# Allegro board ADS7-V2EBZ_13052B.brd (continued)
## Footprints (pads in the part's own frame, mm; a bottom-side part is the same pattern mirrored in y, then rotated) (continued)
CNTYCO292304
  rect 1.524x1.524 hole 1.016: 1(0,0)
  round 1.524 hole 1.016: 2(2.5,0) 3(2.5,2) 4(0,2)
  round 2.921 hole 2.413: G1(-4.77,4.71) G2(7.27,4.71)
CPLSML327W327H413
  rect 4.039x1.397 smd: N(3.43,0) P(-3.43,0)
CSPBGA208
  round 0.356 smd: A1(-7.6,-7.6) A2(-7.6,-6.8) A3(-7.6,-6) A4(-7.6,-5.2) A5(-7.6,-4.4) A6(-7.6,-3.6) A7(-7.6,-2.8) A8(-7.6,-2) A9(-7.6,-1.2) A10(-7.6,-0.4) A11(-7.6,0.4) A12(-7.6,1.2) A13(-7.6,2) A14(-7.6,2.8) A15(-7.6,3.6) A16(-7.6,4.4) A17(-7.6,5.2) A18(-7.6,6) A19(-7.6,6.8) A20(-7.6,7.6) B1(-6.8,-7.6) B2(-6.8,-6.8) B3(-6.8,-6) B4(-6.8,-5.2) B5(-6.8,-4.4) B6(-6.8,-3.6) B7(-6.8,-2.8) B8(-6.8,-2) B9(-6.8,-1.2) B10(-6.8,-0.4) B11(-6.8,0.4) B12(-6.8,1.2) B13(-6.8,2) B14(-6.8,2.8) B15(-6.8,3.6) B16(-6.8,4.4) B17(-6.8,5.2) B18(-6.8,6) B19(-6.8,6.8) B20(-6.8,7.6) C1(-6,-7.6) C2(-6,-6.8) C19(-6,6.8) C20(-6,7.6) D1(-5.2,-7.6) D2(-5.2,-6.8) D19(-5.2,6.8) D20(-5.2,7.6) E1(-4.4,-7.6) E2(-4.4,-6.8) E19(-4.4,6.8) E20(-4.4,7.6) F1(-3.6,-7.6) F2(-3.6,-6.8) F19(-3.6,6.8) F20(-3.6,7.6) G1(-2.8,-7.6) G2(-2.8,-6.8) G7(-2.8,-2.8) G8(-2.8,-2) G9(-2.8,-1.2) G10(-2.8,-0.4) G11(-2.8,0.4) G12(-2.8,1.2) G13(-2.8,2) G14(-2.8,2.8) G19(-2.8,6.8) G20(-2.8,7.6) H1(-2,-7.6) H2(-2,-6.8) H7(-2,-2.8) H8(-2,-2) H9(-2,-1.2) H10(-2,-0.4) H11(-2,0.4) H12(-2,1.2) H13(-2,2) H14(-2,2.8) H19(-2,6.8) H20(-2,7.6) J1(-1.2,-7.6) J2(-1.2,-6.8) J7(-1.2,-2.8) J8(-1.2,-2) J9(-1.2,-1.2) J10(-1.2,-0.4) J11(-1.2,0.4) J12(-1.2,1.2) J13(-1.2,2) J14(-1.2,2.8) J19(-1.2,6.8) J20(-1.2,7.6) K1(-0.4,-7.6) K2(-0.4,-6.8) K7(-0.4,-2.8) K8(-0.4,-2) K9(-0.4,-1.2) K10(-0.4,-0.4) K11(-0.4,0.4) K12(-0.4,1.2) K13(-0.4,2) K14(-0.4,2.8) K19(-0.4,6.8) K20(-0.4,7.6) L1(0.4,-7.6) L2(0.4,-6.8) L7(0.4,-2.8) L8(0.4,-2) L9(0.4,-1.2) L10(0.4,-0.4) L11(0.4,0.4) L12(0.4,1.2) L13(0.4,2) L14(0.4,2.8) L19(0.4,6.8) L20(0.4,7.6) M1(1.2,-7.6) M2(1.2,-6.8) M7(1.2,-2.8) M8(1.2,-2) M9(1.2,-1.2) M10(1.2,-0.4) M11(1.2,0.4) M12(1.2,1.2) M13(1.2,2) M14(1.2,2.8) M19(1.2,6.8) M20(1.2,7.6) N1(2,-7.6) N2(2,-6.8) N7(2,-2.8) N8(2,-2) N9(2,-1.2) N10(2,-0.4) N11(2,0.4) N12(2,1.2) N13(2,2) N14(2,2.8) N19(2,6.8) N20(2,7.6) P1(2.8,-7.6) P2(2.8,-6.8) P7(2.8,-2.8) P8(2.8,-2) P9(2.8,-1.2) P10(2.8,-0.4) P11(2.8,0.4) P12(2.8,1.2) P13(2.8,2) P14(2.8,2.8) P19(2.8,6.8) P20(2.8,7.6) R1(3.6,-7.6) R2(3.6,-6.8) R19(3.6,6.8) R20(3.6,7.6) T1(4.4,-7.6) T2(4.4,-6.8) T19(4.4,6.8) T20(4.4,7.6) U1(5.2,-7.6) U2(5.2,-6.8) U19(5.2,6.8) U20(5.2,7.6) V1(6,-7.6) V2(6,-6.8) V19(6,6.8) V20(6,7.6) W1(6.8,-7.6) W2(6.8,-6.8) W3(6.8,-6) W4(6.8,-5.2) W5(6.8,-4.4) W6(6.8,-3.6) W7(6.8,-2.8) W8(6.8,-2) W9(6.8,-1.2) W10(6.8,-0.4) W11(6.8,0.4) W12(6.8,1.2) W13(6.8,2) W14(6.8,2.8) W15(6.8,3.6) W16(6.8,4.4) W17(6.8,5.2) W18(6.8,6) W19(6.8,6.8) W20(6.8,7.6) Y1(7.6,-7.6) Y2(7.6,-6.8) Y3(7.6,-6) Y4(7.6,-5.2) Y5(7.6,-4.4) Y6(7.6,-3.6) Y7(7.6,-2.8) Y8(7.6,-2) Y9(7.6,-1.2) Y10(7.6,-0.4) Y11(7.6,0.4) Y12(7.6,1.2) Y13(7.6,2) Y14(7.6,2.8) Y15(7.6,3.6) Y16(7.6,4.4) Y17(7.6,5.2) Y18(7.6,6) Y19(7.6,6.8) Y20(7.6,7.6)
D0603
  rect 1.27x0.762 smd: 1(-0.889,0) 2(0.889,0)
DFN8_3X3_PAD2_38X1_64
  oval 0.305x0.838 smd: 1(-0.75,-1.45) 2(-0.25,-1.45) 3(0.25,-1.45) 4(0.75,-1.45) 5(0.75,1.45) 6(0.25,1.45) 7(-0.25,1.45) 8(-0.75,1.45)
  rect 2.388x1.651 smd: PAD(0,0)
DL35
  rect 1.397x1.778 smd: A(1.702,0) C(-1.702,0)
DO214AA1
  rect 1.778x2.184 smd: A(1.968,0) C(-1.968,0)
DQFN16_3_5X2_5_PAD2_15X1_15
  oval 0.889x0.229 smd: 1(-1.795,-0.25) 8(1.795,-0.25) 9(1.795,0.25) 16(-1.795,0.25)
  oval 0.229x0.889 smd: 2(-1.25,-1.294) 3(-0.75,-1.294) 4(-0.25,-1.294) 5(0.25,-1.294) 6(0.75,-1.294) 7(1.25,-1.294) 10(1.25,1.294) 11(0.75,1.294) 12(0.25,1.294) 13(-0.25,1.294) 14(-0.75,1.294) 15(-1.25,1.294)
  rect 1.905x0.991 smd: PAD(0,0)
F1206H30
  rect 1.016x1.803 smd: 1(-1.41,0) 2(1.41,0)
F1206H46
  rect 1.448x1.803 smd: 1(-1.473,0) 2(1.473,0)
F1210_A
  rect 1.194x2.794 smd: 1(-1.5,0) 2(1.5,0)
FBGA1156
  round 0.457 smd: A1(-16.5,-16.5) A2(-16.5,-15.5) A3(-16.5,-14.5) A4(-16.5,-13.5) A5(-16.5,-12.5) A6(-16.5,-11.5) A7(-16.5,-10.5) A8(-16.5,-9.5) A9(-16.5,-8.5) A10(-16.5,-7.5) A11(-16.5,-6.5) A12(-16.5,-5.5) A13(-16.5,-4.5) A14(-16.5,-3.5) A15(-16.5,-2.5) A16(-16.5,-1.5) A17(-16.5,-0.5) A18(-16.5,0.5) A19(-16.5,1.5) A20(-16.5,2.5) A21(-16.5,3.5) A22(-16.5,4.5) A23(-16.5,5.5) A24(-16.5,6.5) A25(-16.5,7.5) A26(-16.5,8.5) A27(-16.5,9.5) A28(-16.5,10.5) A29(-16.5,11.5) A30(-16.5,12.5) A31(-16.5,13.5) A32(-16.5,14.5) A33(-16.5,15.5) A34(-16.5,16.5) AA1(3.5,-16.5) AA2(3.5,-15.5) AA3(3.5,-14.5) AA4(3.5,-13.5) AA5(3.5,-12.5) AA6(3.5,-11.5) AA7(3.5,-10.5) AA8(3.5,-9.5) AA9(3.5,-8.5) AA10(3.5,-7.5) AA11(3.5,-6.5) AA12(3.5,-5.5) AA13(3.5,-4.5) AA14(3.5,-3.5) AA15(3.5,-2.5) AA16(3.5,-1.5) AA17(3.5,-0.5) AA18(3.5,0.5) AA19(3.5,1.5) AA20(3.5,2.5) AA21(3.5,3.5) AA22(3.5,4.5) AA23(3.5,5.5) AA24(3.5,6.5) AA25(3.5,7.5) AA26(3.5,8.5) AA27(3.5,9.5) AA28(3.5,10.5) AA29(3.5,11.5) AA30(3.5,12.5) AA31(3.5,13.5) AA32(3.5,14.5) AA33(3.5,15.5) AA34(3.5,16.5) AB1(4.5,-16.5) AB2(4.5,-15.5) AB3(4.5,-14.5) AB4(4.5,-13.5) AB5(4.5,-12.5) AB6(4.5,-11.5) AB7(4.5,-10.5) AB8(4.5,-9.5) AB9(4.5,-8.5) AB10(4.5,-7.5) AB11(4.5,-6.5) AB12(4.5,-5.5) AB13(4.5,-4.5) AB14(4.5,-3.5) AB15(4.5,-2.5) AB16(4.5,-1.5) AB17(4.5,-0.5) AB18(4.5,0.5) AB19(4.5,1.5) AB20(4.5,2.5) AB21(4.5,3.5) AB22(4.5,4.5) AB23(4.5,5.5) AB24(4.5,6.5) AB25(4.5,7.5) AB26(4.5,8.5) AB27(4.5,9.5) AB28(4.5,10.5) AB29(4.5,11.5) AB30(4.5,12.5) AB31(4.5,13.5) AB32(4.5,14.5) AB33(4.5,15.5) AB34(4.5,16.5) AC1(5.5,-16.5) AC2(5.5,-15.5) AC3(5.5,-14.5) AC4(5.5,-13.5) AC5(5.5,-12.5) AC6(5.5,-11.5) AC7(5.5,-10.5) AC8(5.5,-9.5) AC9(5.5,-8.5) AC10(5.5,-7.5) AC11(5.5,-6.5) AC12(5.5,-5.5) AC13(5.5,-4.5) AC14(5.5,-3.5) AC15(5.5,-2.5) AC16(5.5,-1.5) AC17(5.5,-0.5) AC18(5.5,0.5) AC19(5.5,1.5) AC20(5.5,2.5) AC21(5.5,3.5) AC22(5.5,4.5) AC23(5.5,5.5) AC24(5.5,6.5) AC25(5.5,7.5) AC26(5.5,8.5) AC27(5.5,9.5) AC28(5.5,10.5) AC29(5.5,11.5) AC30(5.5,12.5) AC31(5.5,13.5) AC32(5.5,14.5) AC33(5.5,15.5) AC34(5.5,16.5) AD1(6.5,-16.5) AD2(6.5,-15.5) AD3(6.5,-14.5) AD4(6.5,-13.5) AD5(6.5,-12.5) AD6(6.5,-11.5) AD7(6.5,-10.5) AD8(6.5,-9.5) AD9(6.5,-8.5) AD10(6.5,-7.5) AD11(6.5,-6.5) AD12(6.5,-5.5) AD13(6.5,-4.5) AD14(6.5,-3.5) AD15(6.5,-2.5) AD16(6.5,-1.5) AD17(6.5,-0.5) AD18(6.5,0.5) AD19(6.5,1.5) AD20(6.5,2.5) AD21(6.5,3.5) AD22(6.5,4.5) AD23(6.5,5.5) AD24(6.5,6.5) AD25(6.5,7.5) AD26(6.5,8.5) AD27(6.5,9.5) AD28(6.5,10.5) AD29(6.5,11.5) AD30(6.5,12.5) AD31(6.5,13.5) AD32(6.5,14.5) AD33(6.5,15.5) AD34(6.5,16.5) AE1(7.5,-16.5) AE2(7.5,-15.5) AE3(7.5,-14.5) AE4(7.5,-13.5) AE5(7.5,-12.5) AE6(7.5,-11.5) AE7(7.5,-10.5) AE8(7.5,-9.5) AE9(7.5,-8.5) AE10(7.5,-7.5) AE11(7.5,-6.5) AE12(7.5,-5.5) AE13(7.5,-4.5) AE14(7.5,-3.5) AE15(7.5,-2.5) AE16(7.5,-1.5) AE17(7.5,-0.5) AE18(7.5,0.5) AE19(7.5,1.5) AE20(7.5,2.5) AE21(7.5,3.5) AE22(7.5,4.5) AE23(7.5,5.5) AE24(7.5,6.5) AE25(7.5,7.5) AE26(7.5,8.5) AE27(7.5,9.5) AE28(7.5,10.5) AE29(7.5,11.5) AE30(7.5,12.5) AE31(7.5,13.5) AE32(7.5,14.5) AE33(7.5,15.5) AE34(7.5,16.5) AF1(8.5,-16.5) AF2(8.5,-15.5) AF3(8.5,-14.5) AF4(8.5,-13.5) AF5(8.5,-12.5) AF6(8.5,-11.5) AF7(8.5,-10.5) AF8(8.5,-9.5) AF9(8.5,-8.5) AF10(8.5,-7.5) AF11(8.5,-6.5) AF12(8.5,-5.5) AF13(8.5,-4.5) AF14(8.5,-3.5) AF15(8.5,-2.5) AF16(8.5,-1.5) AF17(8.5,-0.5) AF18(8.5,0.5) AF19(8.5,1.5) AF20(8.5,2.5) AF21(8.5,3.5) AF22(8.5,4.5) AF23(8.5,5.5) AF24(8.5,6.5) AF25(8.5,7.5) AF26(8.5,8.5) AF27(8.5,9.5) AF28(8.5,10.5) AF29(8.5,11.5) AF30(8.5,12.5) AF31(8.5,13.5) AF32(8.5,14.5) AF33(8.5,15.5) AF34(8.5,16.5) AG1(9.5,-16.5) AG2(9.5,-15.5) AG3(9.5,-14.5) AG4(9.5,-13.5) AG5(9.5,-12.5) AG6(9.5,-11.5) AG7(9.5,-10.5) AG8(9.5,-9.5) AG9(9.5,-8.5) AG10(9.5,-7.5) AG11(9.5,-6.5) AG12(9.5,-5.5) AG13(9.5,-4.5) AG14(9.5,-3.5) AG15(9.5,-2.5) AG16(9.5,-1.5) AG17(9.5,-0.5) AG18(9.5,0.5) AG19(9.5,1.5) AG20(9.5,2.5) AG21(9.5,3.5) AG22(9.5,4.5) AG23(9.5,5.5) AG24(9.5,6.5) AG25(9.5,7.5) AG26(9.5,8.5) AG27(9.5,9.5) AG28(9.5,10.5) AG29(9.5,11.5) AG30(9.5,12.5) AG31(9.5,13.5) AG32(9.5,14.5) AG33(9.5,15.5) AG34(9.5,16.5) AH1(10.5,-16.5) AH2(10.5,-15.5) AH3(10.5,-14.5) AH4(10.5,-13.5) AH5(10.5,-12.5) AH6(10.5,-11.5) AH7(10.5,-10.5) AH8(10.5,-9.5) AH9(10.5,-8.5) AH10(10.5,-7.5) AH11(10.5,-6.5) AH12(10.5,-5.5) AH13(10.5,-4.5) AH14(10.5,-3.5) AH15(10.5,-2.5) AH16(10.5,-1.5) AH17(10.5,-0.5) AH18(10.5,0.5) AH19(10.5,1.5) AH20(10.5,2.5) AH21(10.5,3.5) AH22(10.5,4.5) AH23(10.5,5.5) AH24(10.5,6.5) AH25(10.5,7.5) AH26(10.5,8.5) AH27(10.5,9.5) AH28(10.5,10.5) AH29(10.5,11.5) AH30(10.5,12.5) AH31(10.5,13.5) AH32(10.5,14.5) AH33(10.5,15.5) AH34(10.5,16.5) AJ1(11.5,-16.5) AJ2(11.5,-15.5) AJ3(11.5,-14.5) AJ4(11.5,-13.5) AJ5(11.5,-12.5) AJ6(11.5,-11.5) AJ7(11.5,-10.5) AJ8(11.5,-9.5) AJ9(11.5,-8.5) AJ10(11.5,-7.5) AJ11(11.5,-6.5) AJ12(11.5,-5.5) AJ13(11.5,-4.5) AJ14(11.5,-3.5) AJ15(11.5,-2.5) AJ16(11.5,-1.5) AJ17(11.5,-0.5) AJ18(11.5,0.5) AJ19(11.5,1.5) AJ20(11.5,2.5) AJ21(11.5,3.5) AJ22(11.5,4.5) AJ23(11.5,5.5) AJ24(11.5,6.5) AJ25(11.5,7.5) AJ26(11.5,8.5) AJ27(11.5,9.5) AJ28(11.5,10.5) AJ29(11.5,11.5) AJ30(11.5,12.5) AJ31(11.5,13.5) AJ32(11.5,14.5) AJ33(11.5,15.5) AJ34(11.5,16.5) AK1(12.5,-16.5) AK2(12.5,-15.5) AK3(12.5,-14.5) AK4(12.5,-13.5) AK5(12.5,-12.5) AK6(12.5,-11.5) AK7(12.5,-10.5) AK8(12.5,-9.5) AK9(12.5,-8.5) AK10(12.5,-7.5) AK11(12.5,-6.5) AK12(12.5,-5.5) AK13(12.5,-4.5) AK14(12.5,-3.5) AK15(12.5,-2.5) AK16(12.5,-1.5) AK17(12.5,-0.5) AK18(12.5,0.5) AK19(12.5,1.5) AK20(12.5,2.5) AK21(12.5,3.5) AK22(12.5,4.5) AK23(12.5,5.5) AK24(12.5,6.5) AK25(12.5,7.5) AK26(12.5,8.5) AK27(12.5,9.5) AK28(12.5,10.5) AK29(12.5,11.5) AK30(12.5,12.5) AK31(12.5,13.5) AK32(12.5,14.5) AK33(12.5,15.5) AK34(12.5,16.5) AL1(13.5,-16.5) AL2(13.5,-15.5) AL3(13.5,-14.5) AL4(13.5,-13.5) AL5(13.5,-12.5) AL6(13.5,-11.5) AL7(13.5,-10.5) AL8(13.5,-9.5) AL9(13.5,-8.5) AL10(13.5,-7.5) AL11(13.5,-6.5) AL12(13.5,-5.5) AL13(13.5,-4.5) AL14(13.5,-3.5) AL15(13.5,-2.5) AL16(13.5,-1.5) AL17(13.5,-0.5) AL18(13.5,0.5) AL19(13.5,1.5) AL20(13.5,2.5) AL21(13.5,3.5) AL22(13.5,4.5) AL23(13.5,5.5) AL24(13.5,6.5) AL25(13.5,7.5) AL26(13.5,8.5) AL27(13.5,9.5) AL28(13.5,10.5) AL29(13.5,11.5) AL30(13.5,12.5) AL31(13.5,13.5) AL32(13.5,14.5) AL33(13.5,15.5) AL34(13.5,16.5) AM1(14.5,-16.5) AM2(14.5,-15.5) AM3(14.5,-14.5) AM4(14.5,-13.5) AM5(14.5,-12.5) AM6(14.5,-11.5) AM7(14.5,-10.5) AM8(14.5,-9.5) AM9(14.5,-8.5) AM10(14.5,-7.5) AM11(14.5,-6.5) AM12(14.5,-5.5) AM13(14.5,-4.5) AM14(14.5,-3.5) AM15(14.5,-2.5) AM16(14.5,-1.5) AM17(14.5,-0.5) AM18(14.5,0.5) AM19(14.5,1.5) AM20(14.5,2.5) AM21(14.5,3.5) AM22(14.5,4.5) AM23(14.5,5.5) AM24(14.5,6.5) AM25(14.5,7.5) AM26(14.5,8.5) AM27(14.5,9.5) AM28(14.5,10.5) AM29(14.5,11.5) AM30(14.5,12.5) AM31(14.5,13.5) AM32(14.5,14.5) AM33(14.5,15.5) AM34(14.5,16.5) AN1(15.5,-16.5) AN2(15.5,-15.5) AN3(15.5,-14.5) AN4(15.5,-13.5) AN5(15.5,-12.5) AN6(15.5,-11.5) AN7(15.5,-10.5) AN8(15.5,-9.5) AN9(15.5,-8.5) AN10(15.5,-7.5) AN11(15.5,-6.5) AN12(15.5,-5.5) AN13(15.5,-4.5) AN14(15.5,-3.5) AN15(15.5,-2.5) AN16(15.5,-1.5) AN17(15.5,-0.5) AN18(15.5,0.5) AN19(15.5,1.5) AN20(15.5,2.5) AN21(15.5,3.5) AN22(15.5,4.5) AN23(15.5,5.5) AN24(15.5,6.5) AN25(15.5,7.5) AN26(15.5,8.5) AN27(15.5,9.5) AN28(15.5,10.5) AN29(15.5,11.5) AN30(15.5,12.5) AN31(15.5,13.5) AN32(15.5,14.5) AN33(15.5,15.5) AN34(15.5,16.5) AP1(16.5,-16.5) AP2(16.5,-15.5) AP3(16.5,-14.5) AP4(16.5,-13.5) AP5(16.5,-12.5) AP6(16.5,-11.5) AP7(16.5,-10.5) AP8(16.5,-9.5) AP9(16.5,-8.5) AP10(16.5,-7.5) AP11(16.5,-6.5) AP12(16.5,-5.5) AP13(16.5,-4.5) AP14(16.5,-3.5) AP15(16.5,-2.5) AP16(16.5,-1.5) AP17(16.5,-0.5) AP18(16.5,0.5) AP19(16.5,1.5) AP20(16.5,2.5) AP21(16.5,3.5) AP22(16.5,4.5) AP23(16.5,5.5) AP24(16.5,6.5) AP25(16.5,7.5) AP26(16.5,8.5) AP27(16.5,9.5) AP28(16.5,10.5) AP29(16.5,11.5) AP30(16.5,12.5) AP31(16.5,13.5) AP32(16.5,14.5) AP33(16.5,15.5) AP34(16.5,16.5) B1(-15.5,-16.5) B2(-15.5,-15.5) B3(-15.5,-14.5) B4(-15.5,-13.5) B5(-15.5,-12.5) B6(-15.5,-11.5) B7(-15.5,-10.5) B8(-15.5,-9.5) B9(-15.5,-8.5) B10(-15.5,-7.5) B11(-15.5,-6.5) B12(-15.5,-5.5) B13(-15.5,-4.5) B14(-15.5,-3.5) B15(-15.5,-2.5) B16(-15.5,-1.5) B17(-15.5,-0.5) B18(-15.5,0.5) B19(-15.5,1.5) B20(-15.5,2.5) B21(-15.5,3.5) B22(-15.5,4.5) B23(-15.5,5.5) B24(-15.5,6.5) B25(-15.5,7.5) B26(-15.5,8.5) B27(-15.5,9.5) B28(-15.5,10.5) B29(-15.5,11.5) B30(-15.5,12.5) B31(-15.5,13.5) B32(-15.5,14.5) B33(-15.5,15.5) B34(-15.5,16.5) C1(-14.5,-16.5) C2(-14.5,-15.5) C3(-14.5,-14.5) C4(-14.5,-13.5) C5(-14.5,-12.5) C6(-14.5,-11.5) C7(-14.5,-10.5) C8(-14.5,-9.5) C9(-14.5,-8.5) C10(-14.5,-7.5) C11(-14.5,-6.5) C12(-14.5,-5.5) C13(-14.5,-4.5) C14(-14.5,-3.5) C15(-14.5,-2.5) C16(-14.5,-1.5) C17(-14.5,-0.5) C18(-14.5,0.5) C19(-14.5,1.5) C20(-14.5,2.5) C21(-14.5,3.5) C22(-14.5,4.5) C23(-14.5,5.5) C24(-14.5,6.5) C25(-14.5,7.5) C26(-14.5,8.5) C27(-14.5,9.5) C28(-14.5,10.5) C29(-14.5,11.5) C30(-14.5,12.5) C31(-14.5,13.5) C32(-14.5,14.5) C33(-14.5,15.5) C34(-14.5,16.5) D1(-13.5,-16.5) D2(-13.5,-15.5) D3(-13.5,-14.5) D4(-13.5,-13.5) D5(-13.5,-12.5) D6(-13.5,-11.5) D7(-13.5,-10.5) D8(-13.5,-9.5) D9(-13.5,-8.5) D10(-13.5,-7.5) D11(-13.5,-6.5) D12(-13.5,-5.5) D13(-13.5,-4.5) D14(-13.5,-3.5) D15(-13.5,-2.5) D16(-13.5,-1.5) D17(-13.5,-0.5) D18(-13.5,0.5) D19(-13.5,1.5) D20(-13.5,2.5) D21(-13.5,3.5) D22(-13.5,4.5) D23(-13.5,5.5) D24(-13.5,6.5) D25(-13.5,7.5) D26(-13.5,8.5) D27(-13.5,9.5) D28(-13.5,10.5) D29(-13.5,11.5) D30(-13.5,12.5) D31(-13.5,13.5) D32(-13.5,14.5) D33(-13.5,15.5) D34(-13.5,16.5) E1(-12.5,-16.5) E2(-12.5,-15.5) E3(-12.5,-14.5) E4(-12.5,-13.5) E5(-12.5,-12.5) E6(-12.5,-11.5) E7(-12.5,-10.5) E8(-12.5,-9.5) E9(-12.5,-8.5) E10(-12.5,-7.5) E11(-12.5,-6.5) E12(-12.5,-5.5) E13(-12.5,-4.5) E14(-12.5,-3.5) E15(-12.5,-2.5) E16(-12.5,-1.5) E17(-12.5,-0.5) E18(-12.5,0.5) E19(-12.5,1.5) E20(-12.5,2.5) E21(-12.5,3.5) E22(-12.5,4.5) E23(-12.5,5.5) E24(-12.5,6.5) E25(-12.5,7.5) E26(-12.5,8.5) E27(-12.5,9.5) E28(-12.5,10.5) E29(-12.5,11.5) E30(-12.5,12.5) E31(-12.5,13.5) E32(-12.5,14.5) E33(-12.5,15.5) E34(-12.5,16.5) F1(-11.5,-16.5) F2(-11.5,-15.5) F3(-11.5,-14.5) F4(-11.5,-13.5) F5(-11.5,-12.5) F6(-11.5,-11.5) F7(-11.5,-10.5) F8(-11.5,-9.5) F9(-11.5,-8.5) F10(-11.5,-7.5) F11(-11.5,-6.5) F12(-11.5,-5.5) F13(-11.5,-4.5) F14(-11.5,-3.5) F15(-11.5,-2.5) F16(-11.5,-1.5) F17(-11.5,-0.5) F18(-11.5,0.5) F19(-11.5,1.5) F20(-11.5,2.5) F21(-11.5,3.5) F22(-11.5,4.5) F23(-11.5,5.5) F24(-11.5,6.5) F25(-11.5,7.5) F26(-11.5,8.5) F27(-11.5,9.5) F28(-11.5,10.5) F29(-11.5,11.5) F30(-11.5,12.5) F31(-11.5,13.5) F32(-11.5,14.5) F33(-11.5,15.5) F34(-11.5,16.5) G1(-10.5,-16.5) G2(-10.5,-15.5) G3(-10.5,-14.5) G4(-10.5,-13.5) G5(-10.5,-12.5) G6(-10.5,-11.5) G7(-10.5,-10.5) G8(-10.5,-9.5) G9(-10.5,-8.5) G10(-10.5,-7.5) G11(-10.5,-6.5) G12(-10.5,-5.5) G13(-10.5,-4.5) G14(-10.5,-3.5) G15(-10.5,-2.5) G16(-10.5,-1.5) G17(-10.5,-0.5) G18(-10.5,0.5) G19(-10.5,1.5) G20(-10.5,2.5) G21(-10.5,3.5) G22(-10.5,4.5) G23(-10.5,5.5) G24(-10.5,6.5) G25(-10.5,7.5) G26(-10.5,8.5) G27(-10.5,9.5) G28(-10.5,10.5) G29(-10.5,11.5) G30(-10.5,12.5) G31(-10.5,13.5) G32(-10.5,14.5) G33(-10.5,15.5) G34(-10.5,16.5) H1(-9.5,-16.5) H2(-9.5,-15.5) H3(-9.5,-14.5) H4(-9.5,-13.5) H5(-9.5,-12.5) H6(-9.5,-11.5) H7(-9.5,-10.5) H8(-9.5,-9.5) H9(-9.5,-8.5) H10(-9.5,-7.5) H11(-9.5,-6.5) H12(-9.5,-5.5) H13(-9.5,-4.5) H14(-9.5,-3.5) H15(-9.5,-2.5) H16(-9.5,-1.5) H17(-9.5,-0.5) H18(-9.5,0.5) H19(-9.5,1.5) H20(-9.5,2.5) H21(-9.5,3.5) H22(-9.5,4.5) H23(-9.5,5.5) H24(-9.5,6.5) H25(-9.5,7.5) H26(-9.5,8.5) H27(-9.5,9.5) H28(-9.5,10.5) H29(-9.5,11.5) H30(-9.5,12.5) H31(-9.5,13.5) H32(-9.5,14.5) H33(-9.5,15.5) H34(-9.5,16.5) J1(-8.5,-16.5) J2(-8.5,-15.5) J3(-8.5,-14.5) J4(-8.5,-13.5) J5(-8.5,-12.5) J6(-8.5,-11.5) J7(-8.5,-10.5) J8(-8.5,-9.5) J9(-8.5,-8.5) J10(-8.5,-7.5) J11(-8.5,-6.5) J12(-8.5,-5.5) J13(-8.5,-4.5) J14(-8.5,-3.5) J15(-8.5,-2.5) J16(-8.5,-1.5) J17(-8.5,-0.5) J18(-8.5,0.5) J19(-8.5,1.5) J20(-8.5,2.5) J21(-8.5,3.5) J22(-8.5,4.5) J23(-8.5,5.5) J24(-8.5,6.5) J25(-8.5,7.5) J26(-8.5,8.5) J27(-8.5,9.5) J28(-8.5,10.5) J29(-8.5,11.5) J30(-8.5,12.5) J31(-8.5,13.5) J32(-8.5,14.5) J33(-8.5,15.5) J34(-8.5,16.5) K1(-7.5,-16.5) K2(-7.5,-15.5) K3(-7.5,-14.5) K4(-7.5,-13.5) K5(-7.5,-12.5) K6(-7.5,-11.5) K7(-7.5,-10.5) K8(-7.5,-9.5) K9(-7.5,-8.5) K10(-7.5,-7.5) K11(-7.5,-6.5) K12(-7.5,-5.5) K13(-7.5,-4.5) K14(-7.5,-3.5) K15(-7.5,-2.5) K16(-7.5,-1.5) K17(-7.5,-0.5) K18(-7.5,0.5) K19(-7.5,1.5) K20(-7.5,2.5) K21(-7.5,3.5) K22(-7.5,4.5) K23(-7.5,5.5) K24(-7.5,6.5) K25(-7.5,7.5) K26(-7.5,8.5) K27(-7.5,9.5) K28(-7.5,10.5) K29(-7.5,11.5) K30(-7.5,12.5) K31(-7.5,13.5) K32(-7.5,14.5) K33(-7.5,15.5) K34(-7.5,16.5) L1(-6.5,-16.5) L2(-6.5,-15.5) L3(-6.5,-14.5) L4(-6.5,-13.5) L5(-6.5,-12.5) L6(-6.5,-11.5) L7(-6.5,-10.5) L8(-6.5,-9.5) L9(-6.5,-8.5) L10(-6.5,-7.5) L11(-6.5,-6.5) L12(-6.5,-5.5) L13(-6.5,-4.5) L14(-6.5,-3.5) L15(-6.5,-2.5) L16(-6.5,-1.5) L17(-6.5,-0.5) L18(-6.5,0.5) L19(-6.5,1.5) L20(-6.5,2.5) L21(-6.5,3.5) L22(-6.5,4.5) L23(-6.5,5.5) L24(-6.5,6.5) L25(-6.5,7.5) L26(-6.5,8.5) L27(-6.5,9.5) L28(-6.5,10.5) L29(-6.5,11.5) L30(-6.5,12.5) L31(-6.5,13.5) L32(-6.5,14.5) L33(-6.5,15.5) L34(-6.5,16.5) M1(-5.5,-16.5) M2(-5.5,-15.5) M3(-5.5,-14.5) M4(-5.5,-13.5) M5(-5.5,-12.5) M6(-5.5,-11.5) M7(-5.5,-10.5) M8(-5.5,-9.5) M9(-5.5,-8.5) M10(-5.5,-7.5) M11(-5.5,-6.5) M12(-5.5,-5.5) M13(-5.5,-4.5) M14(-5.5,-3.5) M15(-5.5,-2.5) M16(-5.5,-1.5) M17(-5.5,-0.5) M18(-5.5,0.5) M19(-5.5,1.5) M20(-5.5,2.5) M21(-5.5,3.5) M22(-5.5,4.5) M23(-5.5,5.5) M24(-5.5,6.5) M25(-5.5,7.5) M26(-5.5,8.5) M27(-5.5,9.5) M28(-5.5,10.5) M29(-5.5,11.5) M30(-5.5,12.5) M31(-5.5,13.5) M32(-5.5,14.5) M33(-5.5,15.5) M34(-5.5,16.5) N1(-4.5,-16.5) N2(-4.5,-15.5) N3(-4.5,-14.5) N4(-4.5,-13.5) N5(-4.5,-12.5) N6(-4.5,-11.5) N7(-4.5,-10.5) N8(-4.5,-9.5) N9(-4.5,-8.5) N10(-4.5,-7.5) N11(-4.5,-6.5) N12(-4.5,-5.5) N13(-4.5,-4.5) N14(-4.5,-3.5) N15(-4.5,-2.5) N16(-4.5,-1.5) N17(-4.5,-0.5) N18(-4.5,0.5) N19(-4.5,1.5) N20(-4.5,2.5) N21(-4.5,3.5) N22(-4.5,4.5) N23(-4.5,5.5) N24(-4.5,6.5) N25(-4.5,7.5) N26(-4.5,8.5) N27(-4.5,9.5) N28(-4.5,10.5) N29(-4.5,11.5) N30(-4.5,12.5) N31(-4.5,13.5) N32(-4.5,14.5) N33(-4.5,15.5) N34(-4.5,16.5) P1(-3.5,-16.5) P2(-3.5,-15.5) P3(-3.5,-14.5) P4(-3.5,-13.5) P5(-3.5,-12.5) P6(-3.5,-11.5) P7(-3.5,-10.5) P8(-3.5,-9.5) P9(-3.5,-8.5) P10(-3.5,-7.5) P11(-3.5,-6.5) P12(-3.5,-5.5) P13(-3.5,-4.5) P14(-3.5,-3.5) P15(-3.5,-2.5) P16(-3.5,-1.5) P17(-3.5,-0.5) P18(-3.5,0.5) P19(-3.5,1.5) P20(-3.5,2.5) P21(-3.5,3.5) P22(-3.5,4.5) P23(-3.5,5.5) P24(-3.5,6.5) P25(-3.5,7.5) P26(-3.5,8.5) P27(-3.5,9.5) P28(-3.5,10.5) P29(-3.5,11.5) P30(-3.5,12.5) P31(-3.5,13.5) P32(-3.5,14.5) P33(-3.5,15.5) P34(-3.5,16.5) R1(-2.5,-16.5) R2(-2.5,-15.5) R3(-2.5,-14.5) R4(-2.5,-13.5) R5(-2.5,-12.5) R6(-2.5,-11.5) R7(-2.5,-10.5) R8(-2.5,-9.5) R9(-2.5,-8.5) R10(-2.5,-7.5) R11(-2.5,-6.5) R12(-2.5,-5.5) R13(-2.5,-4.5) R14(-2.5,-3.5) R15(-2.5,-2.5) R16(-2.5,-1.5) R17(-2.5,-0.5) R18(-2.5,0.5) R19(-2.5,1.5) R20(-2.5,2.5) R21(-2.5,3.5) R22(-2.5,4.5) R23(-2.5,5.5) R24(-2.5,6.5) R25(-2.5,7.5) R26(-2.5,8.5) R27(-2.5,9.5) R28(-2.5,10.5) R29(-2.5,11.5) R30(-2.5,12.5) R31(-2.5,13.5) R32(-2.5,14.5) R33(-2.5,15.5) R34(-2.5,16.5) T1(-1.5,-16.5) T2(-1.5,-15.5) T3(-1.5,-14.5) T4(-1.5,-13.5) T5(-1.5,-12.5) T6(-1.5,-11.5) T7(-1.5,-10.5) T8(-1.5,-9.5) T9(-1.5,-8.5) T10(-1.5,-7.5) T11(-1.5,-6.5) T12(-1.5,-5.5) T13(-1.5,-4.5) T14(-1.5,-3.5) T15(-1.5,-2.5) T16(-1.5,-1.5) T17(-1.5,-0.5) T18(-1.5,0.5) T19(-1.5,1.5) T20(-1.5,2.5) T21(-1.5,3.5) T22(-1.5,4.5) T23(-1.5,5.5) T24(-1.5,6.5) T25(-1.5,7.5) T26(-1.5,8.5) T27(-1.5,9.5) T28(-1.5,10.5) T29(-1.5,11.5) T30(-1.5,12.5) T31(-1.5,13.5) T32(-1.5,14.5) T33(-1.5,15.5) T34(-1.5,16.5) U1(-0.5,-16.5) U2(-0.5,-15.5) U3(-0.5,-14.5) U4(-0.5,-13.5) U5(-0.5,-12.5) U6(-0.5,-11.5) U7(-0.5,-10.5) U8(-0.5,-9.5) U9(-0.5,-8.5) U10(-0.5,-7.5) U11(-0.5,-6.5) U12(-0.5,-5.5) U13(-0.5,-4.5) U14(-0.5,-3.5) U15(-0.5,-2.5) U16(-0.5,-1.5) U17(-0.5,-0.5) U18(-0.5,0.5) U19(-0.5,1.5) U20(-0.5,2.5) U21(-0.5,3.5) U22(-0.5,4.5) U23(-0.5,5.5) U24(-0.5,6.5) U25(-0.5,7.5) U26(-0.5,8.5) U27(-0.5,9.5) U28(-0.5,10.5) U29(-0.5,11.5) U30(-0.5,12.5) U31(-0.5,13.5) U32(-0.5,14.5) U33(-0.5,15.5) U34(-0.5,16.5) V1(0.5,-16.5) V2(0.5,-15.5) V3(0.5,-14.5) V4(0.5,-13.5) V5(0.5,-12.5) V6(0.5,-11.5) V7(0.5,-10.5) V8(0.5,-9.5) V9(0.5,-8.5) V10(0.5,-7.5) V11(0.5,-6.5) V12(0.5,-5.5) V13(0.5,-4.5) V14(0.5,-3.5) V15(0.5,-2.5) V16(0.5,-1.5) V17(0.5,-0.5) V18(0.5,0.5) V19(0.5,1.5) V20(0.5,2.5) V21(0.5,3.5) V22(0.5,4.5) V23(0.5,5.5) V24(0.5,6.5) V25(0.5,7.5) V26(0.5,8.5) V27(0.5,9.5) V28(0.5,10.5) V29(0.5,11.5) V30(0.5,12.5) V31(0.5,13.5) V32(0.5,14.5) V33(0.5,15.5) V34(0.5,16.5) W1(1.5,-16.5) W2(1.5,-15.5) W3(1.5,-14.5) W4(1.5,-13.5) W5(1.5,-12.5) W6(1.5,-11.5) W7(1.5,-10.5) W8(1.5,-9.5) W9(1.5,-8.5) W10(1.5,-7.5) W11(1.5,-6.5) W12(1.5,-5.5) W13(1.5,-4.5) W14(1.5,-3.5) W15(1.5,-2.5) W16(1.5,-1.5) W17(1.5,-0.5) W18(1.5,0.5) W19(1.5,1.5) W20(1.5,2.5) W21(1.5,3.5) W22(1.5,4.5) W23(1.5,5.5) W24(1.5,6.5) W25(1.5,7.5) W26(1.5,8.5) W27(1.5,9.5) W28(1.5,10.5) W29(1.5,11.5) W30(1.5,12.5) W31(1.5,13.5) W32(1.5,14.5) W33(1.5,15.5) W34(1.5,16.5) Y1(2.5,-16.5) Y2(2.5,-15.5) Y3(2.5,-14.5) Y4(2.5,-13.5) Y5(2.5,-12.5) Y6(2.5,-11.5) Y7(2.5,-10.5) Y8(2.5,-9.5) Y9(2.5,-8.5) Y10(2.5,-7.5) Y11(2.5,-6.5) Y12(2.5,-5.5) Y13(2.5,-4.5) Y14(2.5,-3.5) Y15(2.5,-2.5) Y16(2.5,-1.5) Y17(2.5,-0.5) Y18(2.5,0.5) Y19(2.5,1.5) Y20(2.5,2.5) Y21(2.5,3.5) Y22(2.5,4.5) Y23(2.5,5.5) Y24(2.5,6.5) Y25(2.5,7.5) Y26(2.5,8.5) Y27(2.5,9.5) Y28(2.5,10.5) Y29(2.5,11.5) Y30(2.5,12.5) Y31(2.5,13.5) Y32(2.5,14.5) Y33(2.5,15.5) Y34(2.5,16.5)
JPSLD02
  round 5.842 hole 2.692: 1(0.381,62.992) 2(0.406,0)
L0805
  rect 1.143x1.27 smd: 1(-0.953,0) 2(0.953,0)
L1206-3
  rect 1.6x1.803 smd: 1(-1.397,0) 2(1.397,0)
LEDSML90W55H55
  rect 0.813x0.991 smd: A(1.006,0) C(-1.006,0)
LSML208W216H122
  rect 1.168x4.394 smd: 1(-1.651,0) 2(1.651,0)
LSML250W258H122
  rect 1.422x5.69 smd: 1(-2.019,0) 2(2.019,0)
LSMSQ157H122
  rect 0.965x3.708 smd: 1(-1.181,0) 2(1.181,0)
MLP24_4_5X3_5_PAD3_1X2_1
  oval 0.889x0.229 smd: 1(-2.294,-0.25) 2(-2.294,-0.75) 11(2.294,-0.75) 12(2.294,-0.25) 13(2.294,0.25) 14(2.294,0.75) 23(-2.294,0.75) 24(-2.294,0.25)
  oval 0.229x0.889 smd: 3(-1.75,-1.795) 4(-1.25,-1.795) 5(-0.75,-1.795) 6(-0.25,-1.795) 7(0.25,-1.795) 8(0.75,-1.795) 9(1.25,-1.795) 10(1.75,-1.795) 15(1.75,1.795) 16(1.25,1.795) 17(0.75,1.795) 18(0.25,1.795) 19(-0.25,1.795) 20(-0.75,1.795) 21(-1.25,1.795) 22(-1.75,1.795)
  rect 3.099x2.108 smd: PAD(0,0)
MSOP8
  rect 0.305x1.321 smd: 1(-0.975,-2.3) 2(-0.325,-2.3) 3(0.325,-2.3) 4(0.975,-2.3) 5(0.975,2.3) 6(0.325,2.3) 7(-0.325,2.3) 8(-0.975,2.3)
PG-TDSON-8_A
  rect 0.66x1.194 smd: 1(-1.905,-2.828) 2(-0.635,-2.828) 3(0.635,-2.828) 4(1.905,-2.828)
  custom 0.254x0.254 smd: 5(1.849,0.923) 6(0.833,0.923) 7(-0.833,0.923) 8(-1.849,0.923)
QFN10_1_8X1_4
  oval 0.203x0.889 smd: 1(-0.2,-0.668)
  oval 0.203x0.813 smd: 2(0.2,-0.706) 6(0.2,0.706) 7(-0.2,0.706)
  oval 0.813x0.203 smd: 3(0.907,-0.4) 4(0.907,0) 5(0.907,0.4) 8(-0.907,0.4) 9(-0.907,0) 10(-0.907,-0.4)
QFN16_3X3_PAD1_5X1_5
  oval 0.305x0.889 smd: 1(-0.75,-1.5) 2(-0.25,-1.5) 3(0.25,-1.5) 4(0.75,-1.5) 9(0.75,1.5) 10(0.25,1.5) 11(-0.25,1.5) 12(-0.75,1.5)
  oval 0.889x0.305 smd: 5(1.5,-0.75) 6(1.5,-0.25) 7(1.5,0.25) 8(1.5,0.75) 13(-1.5,0.75) 14(-1.5,0.25) 15(-1.5,-0.25) 16(-1.5,-0.75)
  rect 1.499x1.499 smd: PAD(0,0)
QFN16_4X4_PAD2_65X2_65
  oval 0.356x1.041 smd: 1(-0.975,-2.045) 2(-0.325,-2.045) 3(0.325,-2.045) 4(0.975,-2.045) 9(0.975,2.045) 10(0.325,2.045) 11(-0.325,2.045) 12(-0.975,2.045)
  oval 1.041x0.356 smd: 5(2.045,-0.975) 6(2.045,-0.325) 7(2.045,0.325) 8(2.045,0.975) 13(-2.045,0.975) 14(-2.045,0.325) 15(-2.045,-0.325) 16(-2.045,-0.975)
  rect 2.642x2.642 smd: PAD(0,0)
QFN20_5X5_PAD3_1X3_1
  oval 0.305x1.041 smd: 1(-1.3,-2.35) 2(-0.65,-2.35) 3(0,-2.35) 4(0.65,-2.35) 5(1.3,-2.35) 11(1.3,2.35) 12(0.65,2.35) 13(0,2.35) 14(-0.65,2.35) 15(-1.3,2.35)
  oval 1.041x0.305 smd: 6(2.35,-1.3) 7(2.35,-0.65) 8(2.35,0) 9(2.35,0.65) 10(2.35,1.3) 16(-2.35,1.3) 17(-2.35,0.65) 18(-2.35,0) 19(-2.35,-0.65) 20(-2.35,-1.3)
  rect 3.099x3.099 smd: PAD(0,0)
QFN40_6X6_PAD4_6X4_6
  oval 0.305x0.94 smd: 1(-2.25,-3.005) 2(-1.75,-3.005) 3(-1.25,-3.005) 4(-0.75,-3.005) 5(-0.25,-3.005) 6(0.25,-3.005) 7(0.75,-3.005) 8(1.25,-3.005) 9(1.75,-3.005) 10(2.25,-3.005) 21(2.25,3.005) 22(1.75,3.005) 23(1.25,3.005) 24(0.75,3.005) 25(0.25,3.005) 26(-0.25,3.005) 27(-0.75,3.005) 28(-1.25,3.005) 29(-1.75,3.005) 30(-2.25,3.005)
  oval 0.94x0.305 smd: 11(3.005,-2.25) 12(3.005,-1.75) 13(3.005,-1.25) 14(3.005,-0.75) 15(3.005,-0.25) 16(3.005,0.25) 17(3.005,0.75) 18(3.005,1.25) 19(3.005,1.75) 20(3.005,2.25) 31(-3.005,2.25) 32(-3.005,1.75) 33(-3.005,1.25) 34(-3.005,0.75) 35(-3.005,0.25) 36(-3.005,-0.25) 37(-3.005,-0.75) 38(-3.005,-1.25) 39(-3.005,-1.75) 40(-3.005,-2.25)
  rect 4.597x4.597 smd: PAD(0,0)
QFN48_7X7_PAD5_6X5_6
  oval 0.305x0.94 smd: 1(-2.75,-3.5) 2(-2.25,-3.5) 3(-1.75,-3.5) 4(-1.25,-3.5) 5(-0.75,-3.5) 6(-0.25,-3.5) 7(0.25,-3.5) 8(0.75,-3.5) 9(1.25,-3.5) 10(1.75,-3.5) 11(2.25,-3.5) 12(2.75,-3.5) 25(2.75,3.5) 26(2.25,3.5) 27(1.75,3.5) 28(1.25,3.5) 29(0.75,3.5) 30(0.25,3.5) 31(-0.25,3.5) 32(-0.75,3.5) 33(-1.25,3.5) 34(-1.75,3.5) 35(-2.25,3.5) 36(-2.75,3.5)
  oval 0.94x0.305 smd: 13(3.5,-2.75) 14(3.5,-2.25) 15(3.5,-1.75) 16(3.5,-1.25) 17(3.5,-0.75) 18(3.5,-0.25) 19(3.5,0.25) 20(3.5,0.75) 21(3.5,1.25) 22(3.5,1.75) 23(3.5,2.25) 24(3.5,2.75) 37(-3.5,2.75) 38(-3.5,2.25) 39(-3.5,1.75) 40(-3.5,1.25) 41(-3.5,0.75) 42(-3.5,0.25) 43(-3.5,-0.25) 44(-3.5,-0.75) 45(-3.5,-1.25) 46(-3.5,-1.75) 47(-3.5,-2.25) 48(-3.5,-2.75)
  rect 5.588x5.588 smd: PAD(0,0)
R0201
  rect 0.305x0.406 smd: 1(-0.318,0) 2(0.318,0)
R0402
  rect 0.889x0.813 smd: 1(-0.635,0) 2(0.635,0)
R0603
  rect 1.092x1.194 smd: 1(-0.851,0) 2(0.851,0)
R0603H35
  rect 0.813x0.813 smd: 1(-0.907,0) 2(0.907,0)
R0805
  rect 1.295x1.397 smd: 1(-0.953,0) 2(0.953,0)
R1206
  rect 1.6x1.6 smd: 1(-1.397,0) 2(1.397,0)
R2512H31
  rect 2.159x3.556 smd: 1(-2.6,0) 2(2.6,0)
RM10
  rect 0.305x1.321 smd: 1(-1,-2.171) 2(-0.5,-2.171) 3(0,-2.171) 4(0.5,-2.171) 5(1,-2.171) 6(1,2.171) 7(0.5,2.171) 8(0,2.171) 9(-0.5,2.171) 10(-1,2.171)
RN2HV
  rect 0.305x0.813 smd: 1(-1.75,-0.9) 2(-1.25,-0.9) 3(-0.75,-0.9) 4(-0.25,-0.9) 5(0.25,-0.9) 6(0.75,-0.9) 7(1.25,-0.9) 8(1.75,-0.9) 9(1.75,0.9) 10(1.25,0.9) 11(0.75,0.9) 12(0.25,0.9) 13(-0.25,0.9) 14(-0.75,0.9) 15(-1.25,0.9) 16(-1.75,0.9)
SC70
  rect 0.406x0.508 smd: 1(-0.65,-0.95) 2(0,-0.95) 3(0.65,-0.95) 4(0.65,0.95) 5(0,0.95) 6(-0.65,0.95)
SC70-5-2
  rect 0.406x0.508 smd: 1(-0.65,-0.95) 2(0,-0.95) 3(0.65,-0.95) 4(0.65,0.95) 5(-0.65,0.95)
SMC
  rect 2.794x3.81 smd: A(3.569,0) C(-3.569,0)
SO8
  rect 0.61x2.184 smd: 1(-1.905,-2.54) 2(-0.635,-2.54) 3(0.635,-2.54) 4(1.905,-2.54) 5(1.905,2.54) 6(0.635,2.54) 7(-0.635,2.54) 8(-1.905,2.54)
SOD123
  rect 1.702x0.813 smd: A(1.778,0) C(-1.778,0)
SON10_3X3_PAD2_4X1_65
  oval 0.279x0.838 smd: 1(-1,-1.456) 2(-0.5,-1.456) 3(0,-1.456) 4(0.5,-1.456) 5(1,-1.456) 6(1,1.456) 7(0.5,1.456) 8(0,1.456) 9(-0.5,1.456) 10(-1,1.456)
  custom 0.413x0.413 smd: PAD(0,0)
SOP8_A
  rect 0.61x1.6 smd: 1(-1.905,-3.594) 2(-0.635,-3.594) 3(0.635,-3.594) 4(1.905,-3.594) 5(1.905,3.594) 6(0.635,3.594) 7(-0.635,3.594) 8(-1.905,3.594)
SOT23
  rect 1.016x1.397 smd: 1(-0.94,-1.118) 2(0.94,-1.118) 3(0,1.118)
SOT23-5L
  rect 0.508x1.524 smd: 1(-0.95,-1.17) 2(0,-1.17) 3(0.95,-1.17) 4(0.95,1.17) 5(-0.95,1.17)
SOT669
  rect 0.711x1.143 smd: 1(-1.905,-2.829) 2(-0.635,-2.829) 3(0.635,-2.829) 4(1.905,-2.829)
  custom 1.149x1.149 smd: PAD(0,1.101)
SOT873-1
  rect 0.406x0.94 smd: 1(-0.975,-1.55) 2(-0.325,-1.55) 3(0.325,-1.55) 4(0.975,-1.55) 5(0.975,1.55) 6(0.325,1.55) 7(-0.325,1.55) 8(-0.975,1.55)
SWPANASONIC_EVQPA
  rect 1.651x1.651 hole 1.143: 1(0,0)
  round 1.651 hole 1.143: 2(6.5,0) 3(0,4.5) 4(6.5,4.5)
SWSML578W295H214
  rect 1.499x2.159 smd: 1(-5.08,-4.128) 2(-2.54,-4.128) 3(0,-4.128) 4(2.54,-4.128) 5(5.08,-4.128) 6(5.08,4.128) 7(2.54,4.128) 8(0,4.128) 9(-2.54,4.128) 10(-5.08,4.128)
SWTHRAL500W900H450
  rect 2.413x2.413 hole 1.905: 1(0,0)
  round 2.413 hole 1.905: 2(4.699,0) 3(9.398,0) 4(0,-3.81) 5(4.699,-3.81) 6(9.398,-3.81)
  round 2.159 hole 1.651: GND1(-1.905,12.7) GND2(11.303,12.7)
TPC45D22
  round 1.143 hole 0.559: 1(0,0)
TSOT23_6
  rect 0.61x1.219 smd: 1(-0.95,-1.31) 2(0,-1.31) 3(0.95,-1.31) 4(0.95,1.31) 5(0,1.31) 6(-0.95,1.31)
TSOT-5
  rect 0.508x1.524 smd: 1(-0.95,-1.17) 2(0,-1.17) 3(0.95,-1.17) 4(0.95,1.17) 5(-0.95,1.17)
TSOT-8
  rect 0.406x1.067 smd: 1(-0.975,-1.3) 2(-0.325,-1.3) 3(0.325,-1.3) 4(0.975,-1.3) 5(0.975,1.3) 6(0.325,1.3) 7(-0.325,1.3) 8(-0.975,1.3)
TSSOP16
  rect 0.33x1.651 smd: 1(-2.275,-2.92) 2(-1.625,-2.92) 3(-0.975,-2.92) 4(-0.325,-2.92) 5(0.325,-2.92) 6(0.975,-2.92) 7(1.625,-2.92) 8(2.275,-2.92) 9(2.275,2.92) 10(1.625,2.92) 11(0.975,2.92) 12(0.325,2.92) 13(-0.325,2.92) 14(-0.975,2.92) 15(-1.625,2.92) 16(-2.275,2.92)
TSSOP20
  rect 0.33x1.651 smd: 1(-2.925,-2.93) 2(-2.275,-2.93) 3(-1.625,-2.93) 4(-0.975,-2.93) 5(-0.325,-2.93) 6(0.325,-2.93) 7(0.975,-2.93) 8(1.625,-2.93) 9(2.275,-2.93) 10(2.925,-2.93) 11(2.925,2.93) 12(2.275,2.93) 13(1.625,2.93) 14(0.975,2.93) 15(0.325,2.93) 16(-0.325,2.93) 17(-0.975,2.93) 18(-1.625,2.93) 19(-2.275,2.93) 20(-2.925,2.93)
unnamed#2
  round 4.191 hole 2.921 unplated: (0,0)
unnamed#3
  rect 2.032x7.112 smd: (-1.016,-3.327) (-1.016,-16.027) (-1.016,-28.727) (77.216,-9.677) (77.216,-22.377) (77.216,-35.077)
  rect 7.112x2.032 smd: (3.327,-39.116) (9.677,1.016) (16.027,-39.116) (22.377,1.016) (28.727,-39.116) (35.077,1.016) (41.427,-39.116) (47.777,1.016) (54.127,-39.116) (60.477,1.016) (66.827,-39.116) (73.177,1.016)
US8
  rect 0.305x0.711 smd: 1(-0.75,-1.343) 2(-0.25,-1.343) 3(0.25,-1.343) 4(0.75,-1.343) 5(0.75,1.343) 6(0.25,1.343) 7(-0.25,1.343) 8(-0.75,1.343)
YSML126W98H29
  rect 1.295x1.092 smd: 1(-1.148,-0.946) 2(1.148,-0.946) 3(1.148,0.946) 4(-1.148,0.946)
YSML197W126H59
  rect 2.007x2.388 smd: 1(-2.003,0) 2(2.003,0)

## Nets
DGND: C1.2(N2) C2.1(N1) C3.1(N1) C4.2(N2) C5.2(N2) C6.2(N2) C7.2(N2) C8.2(N2) C9.2(N2) C10.2(N2) C11.2(N2) C13.2(N2) C14.2(N2) C15.2(N2) C16.2(N2) C17.2(N2) C19.2(N2) C20.2(N2) C22.2(N2) C23.2(N2) C25.2(N2) C26.2(N2) C27.2(N2) C28.2(N2) C29.1(N1) C30.2(N2) C31.2(N2) C32.2(N2) C33.2(N2) C34.2(N2) C35.2(N2) C36.1(N1) C37.2(N2) C38.1(N1) C39.2(N2) C40.2(N2) C41.2(N2) C42.2(N2) C43.2(N2) C44.2(N2) C45.1(N1) C46.2(N2) C47.1(N1) C48.1(N1) C49.1(N1) C50.1(N1) C51.1(N1) C52.1(N1) C53.1(N1) C54.1(N1) C55.1(N1) C58.N(N2) C60.1(N1) C61.1(N1) C62.1(N1) C64.1(N1) C65.1(N1) C66.1(N1) C67.2(N2) C68.2(N2) C73.2(N2) C74.2(N2) C79.1(N1) C80.1(N1) C81.1(N1) C82.1(N1) C83.1(N1) C84.2(N2) C85.2(N2) C86.2(N2) C87.1(N1) C88.1(N1) C89.1(N1) C90.2(N2) C91.2(N2) C92.2(N2) C93.2(N2) C94.2(N2) C95.2(N2) C96.1(N1) C97.N(N2) C98.2(N2) C99.2(N2) C100.1(N1) C101.2(N2) C102.2(N2) C103.N(N2) C104.2(N2) C105.2(N2) C106.2(N2) C109.2(N2) C112.2(N2) C113.1(N1) C114.1(N1) C115.2(N2) C116.1(N1) C117.1(N1) C118.2(N2) C119.2(N2) C120.N(N2) C122.2(N2) C123.2(N2) C125.2(N2) C126.2(N2) C128.2(N2) C129.2(N2) C130.1(N1) C131.1(N1) C132.1(N1) C133.2(N2) C134.1(N1) C135.1(N1) C136.1(N1) C137.1(N1) C138.1(N1) C139.1(N1) C140.1(N1) C141.1(N1) C142.1(N1) C143.1(N1) C148.2(N2) C149.1(N1) C150.1(N1) C151.2(N2) C152.2(N2) C153.2(N2) C154.2(N2) C155.2(N2) C156.2(N2) C157.2(N2) C158.2(N2) C159.2(N2) C160.2(N2) C161.2(N2) C162.2(N2) C163.1(N1) C164.1(N1) C165.1(N1) C166.1(N1) C167.1(N1) C168.1(N1) C169.1(N1) C170.1(N1) C171.1(N1) C172.1(N1) C173.1(N1) C174.2(N2) C175.2(N2) C176.2(N2) C177.1(N1) C178.1(N1) C179.1(N1) C180.1(N1) C181.1(N1) C182.1(N1) C183.1(N1) C184.1(N1) C185.1(N1) C186.N(N2) C187.1(N1) C188.1(N1) C189.1(N1) C192.1(N1) C193.2(N2) C194.1(N1) C195.1(N1) C196.1(N1) C197.1(N1) C198.1(N1) C199.2(N2) C200.1(N1) C201.1(N1) C202.1(N1) C203.1(N1) C204.1(N1) C205.1(N1) C206.2(N2) C207.2(N2) C208.2(N2) C209.2(N2) C210.2(N2) C211.2(N2) C212.1(N1) C213.1(N1) C214.1(N1) C215.1(N1) C216.1(N1) C217.1(N1) C218.1(N1) C219.1(N1) C220.1(N1) C222.1(N1) C226.2(N2) C227.2(N2) C228.1(N1) C229.1(N1) C230.1(N1) C231.1(N1) C232.1(N1) C234.1(N1) C236.2(N2) C238.2(N2) C239.1(N1) C240.1(N1) C241.1(N1) C242.1(N1) C243.1(N1) C244.2(N2) C245.2(N2) C246.2(N2) C247.2(N2) C248.2(N2) C249.1(N1) C250.1(N1) C251.1(N1) C252.1(N1) C253.1(N1) C254.1(N1) C255.2(N2) C256.2(N2) C257.2(N2) C258.2(N2) C259.2(N2) C260.2(N2) C261.2(N2) C262.1(N1) C263.1(N1) C264.1(N1) C265.1(N1) C266.2(N2) C267.2(N2) C268.2(N2) C269.2(N2) C270.1(N1) C271.1(N1) C272.1(N1) C273.1(N1) C274.1(N1) C275.2(N2) C276.2(N2) C277.2(N2) C278.2(N2) C279.2(N2) C280.2(N2) C284.1(N1) C285.1(N1) C286.1(N1) C287.1(N1) C288.1(N1) C289.1(N1) C290.1(N1) C291.N(N2) C292.1(N1) C293.1(N1) C294.1(N1) C295.1(N1) C296.1(N1) C297.1(N1) C298.1(N1) C299.1(N1) C300.1(N1) C301.1(N1) C303.1(N1) C304.1(N1) C305.1(N1) C306.1(N1) C307.1(N1) C309.1(N1) C310.1(N1) C311.1(N1) C312.1(N1) C313.N(N2) C314.1(N1) C315.1(N1) C316.1(N1) C317.1(N1) C318.1(N1) C320.1(N1) C321.1(N1) C322.1(N1) C323.1(N1) C324.1(N1) C325.1(N1) C326.2(N2) C332.1(N1) C333.1(N1) C334.1(N1) C335.2(N2) C336.1(N1) C337.1(N1) C338.1(N1) C339.1(N1) C340.2(N2) C341.1(N1) C342.2(N2) C343.2(N2) C344.1(N1) C345.1(N1) C346.1(N1) C347.1(N1) C348.1(N1) CN1.1(N1) CN1.2(N2) CN1.3(N3) CN1.4(N4) CN2.1(N1) CN2.2(N2) CN2.3(N3) CN2.4(N4) CN3.1(N1) CN3.2(N2) CN3.3(N3) CN3.4(N4) CN4.1(N1) CN4.2(N2) CN4.3(N3) CN4.4(N4) CN7.1(N1) CN7.2(N2) CN7.3(N3) CN7.4(N4) CN8.1(N1) CN8.2(N2) CN8.3(N3) CN8.4(N4) CN9.1(N1) CN9.2(N2) CN9.3(N3) CN9.4(N4) CN10.1(N1) CN10.2(N2) CN10.3(N3) CN10.4(N4) CN11.1(N1) CN11.2(N2) CN11.3(N3) CN11.4(N4) CN12.1(N1) CN12.2(N2) CN12.3(N3) CN12.4(N4) CN13.1(N1) CN13.2(N2) CN13.3(N3) CN13.4(N4) CN14.1(N1) CN14.2(N2) CN14.3(N3) CN14.4(N4) CR1.A(P) CR2.2(N2) CR4.2(N2) CR5.2(N2) D1.A(P) D2.A(P) DS1.C(N) DS2.C(N) DS3.C(N) DS4.C(N) DS5.C(N) DS6.C(N) DS7.C(N) DS8.C(N) DS14.C(N) DS15.C(N) DS16.C(N) DS18.C(N) E2.2(N2) E3.1(N1) GP1.1(N1) GP1.2(N2) J3.2(SH1) J3.3(SH2) J3.4(SH3) J3.5(SH4) J4.2(SH1) J4.3(SH2) J4.4(SH3) J4.5(SH4) J5.2(SH1) J5.3(SH2) J5.4(SH3) J5.5(SH4) J6.2(SH1) J6.3(SH2) J6.4(SH3) J6.5(SH4) P1.A1(N1) P1.A4(N4) P1.A5(N5) P1.A8(N8) P1.A9(N9) P1.A12(N12) P1.A13(N13) P1.A16(N16) P1.A17(N17) P1.A20(N20) P1.A21(N21) P1.A24(N24) P1.A25(N25) P1.A28(N28) P1.A29(N29) P1.A32(N32) P1.A33(N33) P1.A36(N36) P1.A37(N37) P1.A40(N40) P1.B2(N2) P1.B3(N3) P1.B6(N6) P1.B7(N7) P1.B10(N10) P1.B11(N11) P1.B14(N14) P1.B15(N15) P1.B18(N18) P1.B19(N19) P1.B22(N22) P1.B23(N23) P1.B26(N26) P1.B27(N27) P1.B30(N30) P1.B31(N31) P1.B34(N34) P1.B35(N35) P1.B38(N38) P1.B39(N39) P1.C1(N1) P1.C4(N4) P1.C5(N5) P1.C8(N8) P1.C9(N9) P1.C12(N12) P1.C13(N13) P1.C16(N16) P1.C17(N17) P1.C20(N20) P1.C21(N21) P1.C24(N24) P1.C25(N25) P1.C28(N28) P1.C29(N29) P1.C32(N32) P1.C33(N33) P1.C34(N34) P1.C36(N36) P1.C38(N38) P1.C40(N40) P1.D2(N2) P1.D3(N3) P1.D6(N6) P1.D7(N7) P1.D10(N10) P1.D13(N13) P1.D16(N16) P1.D19(N19) P1.D22(N22) P1.D25(N25) P1.D28(N28) P1.D35(N35) P1.D37(N37) P1.D39(N39) P1.E1(N1) P1.E4(N4) P1.E5(N5) P1.E8(N8) P1.E11(N11) P1.E14(N14) P1.E17(N17) P1.E20(N20) P1.E23(N23) P1.E26(N26) P1.E29(N29) P1.E32(N32) P1.E35(N35) P1.E38(N38) P1.E40(N40) P1.F2(N2) P1.F3(N3) P1.F6(N6) P1.F9(N9) P1.F12(N12) P1.F15(N15) P1.F18(N18) P1.F21(N21) P1.F24(N24) P1.F27(N27) P1.F30(N30) P1.F33(N33) P1.F36(N36) P1.F39(N39) P1.G1(N1) P1.G4(N4) P1.G5(N5) P1.G8(N8) P1.G11(N11) P1.G14(N14) P1.G17(N17) P1.G20(N20) P1.G23(N23) P1.G26(N26) P1.G29(N29) P1.G32(N32) P1.G35(N35) P1.G38(N38) P1.G40(N40) P1.H3(N3) P1.H6(N6) P1.H9(N9) P1.H12(N12) P1.H15(N15) P1.H18(N18) P1.H21(N21) P1.H24(N24) P1.H27(N27) P1.H30(N30) P1.H33(N33) P1.H36(N36) P1.H39(N39) P1.J1(N1) P1.J4(N4) P1.J5(N5) P1.J8(N8) P1.J11(N11) P1.J14(N14) P1.J17(N17) P1.J20(N20) P1.J23(N23) P1.J26(N26) P1.J29(N29) P1.J32(N32) P1.J35(N35) P1.J38(N38) P1.J40(N40) P1.K2(N2) P1.K3(N3) P1.K6(N6) P1.K9(N9) P1.K12(N12) P1.K15(N15) P1.K18(N18) P1.K21(N21) P1.K24(N24) P1.K27(N27) P1.K30(N30) P1.K33(N33) P1.K36(N36) P1.K39(N39) P2.1(N1) P3.1(N1) P3.3(N3) P3.5(N5) P3.7(N7) P3.9(N9) P3.11(N11) P3.13(N13) P5.2(N1) P5.3(N2) P5.8(N4) P5.9(N5) P5.13(N7) P5.14(N7) P5.19(N10) P5.20(N10) P5.25(N13) P5.26(N13) P5.31(N16) P5.32(N16) P5.37(N19) P5.38(N19) P5.43(N22) P5.44(N22) P5.48(N24) P5.49(N25) P5.54(N27) P5.55(N28) P5.60(N30) P5.61(N31) P5.65(N33) P5.66(N33) P5.71(N36) P5.72(N36) P5.127(N65) P5.128(N65) P5.133(N68) P5.134(N68) P5.138(N70) P5.139(N38) P5.144(N40) P5.145(N41) P5.150(N43) P5.151(N44) P5.155(N46) P5.156(N46) P5.161(N49) P5.162(N49) P5.167(N52) P5.168(N52) P5.172(N54) P5.173(N55) P5.178(N57) P5.179(N58) P5.184(N60) P5.185(N61) P5.189(N63) P5.190(N63) P5.195(N66) P5.196(N66) P5.GND1(N37) P5.GND2(N37) P6.2(N1) P6.3(N2) P6.8(N4) P6.9(N5) P6.13(N7) P6.14(N7) P6.19(N10) P6.20(N10) P6.25(N13) P6.26(N13) P6.31(N16) P6.32(N16) P6.37(N19) P6.38(N19) P6.43(N22) P6.44(N22) P6.48(N24) P6.49(N25) P6.54(N27) P6.55(N28) P6.60(N30) P6.61(N31) P6.65(N33) P6.66(N33) P6.71(N36) P6.72(N36) P6.127(N65) P6.128(N65) P6.133(N68) P6.134(N68) P6.138(N70) P6.139(N38) P6.144(N40) P6.145(N41) P6.150(N43) P6.151(N44) P6.155(N46) P6.156(N46) P6.161(N49) P6.162(N49) P6.167(N52) P6.168(N52) P6.172(N54) P6.173(N55) P6.178(N57) P6.179(N58) P6.184(N60) P6.185(N61) P6.189(N63) P6.190(N63) P6.195(N66) P6.196(N66) P6.197(N67) P6.GND1(N37) P6.GND2(N37) P7.3(N3) P7.6(N6) P9.1(N1) P9.3(N3) P9.5(N5) P9.7(N7) P9.9(N9) P9.11(N11) P9.13(N13) P9.15(N15) P9.17(N17) P9.19(N19) P10.1(N1) P10.4(N2) P10.7(N4) P10.9(N5) P10.11(N6) P10.13(N7) P11.1(N1) Q1.1(S) Q1.3(S) Q2.1(S) Q2.3(S) Q7.1(S) Q7.3(S) Q10.2(S) Q13.2(S) Q14.2(S) Q15.2(S) Q16.2(S) R7.2(N2) R9.2(N2) R10.2(N2) R14.2(N2) R15.2(N2) R18.1(N1) R24.2(N2) R33.2(N2) R34.2(N2) R37.2(N2) R43.2(N2) R44.2(N2) R45.2(N2) R46.1(N1) R51.1(N1) R53.1(N1) R55.1(N1) R56.1(N1) R57.1(N1) R60.1(N1) R63.1(N1) R64.1(N1) R66.2(N2) R69.1(N1) R71.1(N1) R72.1(N1) R74.1(N1) R75.1(N1) R77.1(N1) R78.1(N1) R79.1(N1) R82.1(N1) R83.1(N1) R86.1(N1) R87.1(N1) R90.1(N1) R94.1(N1) R97.1(N1) R98.1(N1) R99.2(N2) R100.1(N1) R101.2(N2) R102.1(N1) R103.2(N2) R105.1(N1) R107.2(N2) R110.1(N1) R112.2(N2) R122.2(N2) R124.2(N2) R129.2(N2) R139.2(N2) R143.2(N2) R145.2(N2) R154.2(N2) R155.2(N2) R164.2(N2) R168.1(N1) R170.2(N2) R174.2(N2) R189.1(N1) R200.1(N1) R207.2(N2) R213.2(N2) R215.2(N2) R216.1(N1) R217.1(N1) R220.2(N2) R221.1(N1) R222.2(N2) R225.1(N1) R226.1(N1) R233.2(N2) R237.1(N1) R238.1(N1) R241.1(N1) R242.1(N1) R243.1(N1) R247.1(N1) R248.1(N1) R250.1(N1) R252.1(N1) R254.1(N1) R258.1(N1) R267.2(N2) R268.1(N1) R269.1(N1) R270.1(N1) R274.1(N1) R277.2(N2) R278.2(N2) R279.2(N2) R280.2(N2) R281.1(N1) R282.1(N1) R293.1(N1) R296.2(N2) R297.1(N1) R306.2(N2) R312.1(N1) R313.1(N1) R314.2(N2) R320.1(N1) R325.1(N1) R328.1(N1) R329.1(N1) R330.1(N1) R332.1(N1) R333.1(N1) R337.1(N1) R340.2(N2) R341.2(N2) R486.1(N1) R538.1(N1) R556.1(N1) R664.1(N1) S1.3(NO1) S1.6(NO2) S1.GND1 S1.GND2 S2.1(N1) S2.2(N2) S3.1(N1) S3.2(N2) S5.1(N1) S5.2(N2) S6.1(N1) S6.2(N2) TP1.1(N1) TP2.1(N1) TP3.1(N1) TP5.1(N1) TP6.1(N1) TP7.1(N1) U1.2(PGND3_1) U1.3(PGND3_2) U1.10(PGND4_1) U1.11(PGND4_2) U1.30(PGND) U1.PAD(EP) U2.2(PGND3_1) U2.3(PGND3_2) U2.10(PGND4_1) U2.11(PGND4_2) U2.14(EN4) U2.16(FB4) U2.19(FB2) U2.21(EN2) U2.30(PGND) U2.PAD(EP) U3.3(ADR1) U3.15(GND) U3.16(VAUX) U3.PAD(EPAD) U4.15(GND) U4.16(VAUX) U4.PAD(EPAD) U5.15(GND) U5.16(VAUX) U5.PAD(EPAD) U6.15(GND) U6.16(VAUX) U6.PAD(EPAD) U7.15(GND) U7.16(VAUX) U7.PAD(EPAD) U8.15(GND) U8.16(VAUX) U8.PAD(EPAD) U9.7(ADR) U9.15(GND) U9.PAD U10.4(GND) U10.8(ADR) U11.5(VEE1) U11.16(VEE) U11.PAD U12.6(REFCLK) U12.15(GND1) U12.16(GND2) U12.35(GND3) U12.36(GND4) U12.39(TST2A) U12.PAD U13.5(VEE1) U13.16(VEE) U13.PAD U14.4(ADR2) U14.15(GND) U14.16(VAUX) U14.PAD(EPAD) U15.4(ADR2) U15.15(GND) U15.16(VAUX) U15.PAD(EPAD) U16.4(ADR2) U16.15(GND) U16.16(VAUX) U16.PAD(EPAD) U17.2(GND) U18.3(GND1) U18.6(GND2) U18.PAD U19.2(GND) U20.2(GND) U21.5(GND1) U21.6(GND2) U21.7(GND3) U21.8(GND4) U22.2(OE_N) U22.3(GND) U23.4(GND) U23.5(A2) U23.6(B2) U24.2(GND) U25.4(GND) U25.5(A2) U25.6(B2) U26.3(GND) U27.2(PGND3_1) U27.3(PGND3_2) U27.10(PGND4_1) U27.11(PGND4_2) U27.19(FB2) U27.21(EN2) U27.30(PGND) U27.PAD(EP) U28.2(T_R0_N) U28.7(T_R3_N) U28.8(GND) U28.9(OE_N) U28.10(T_R2_N) U28.PAD U29.A1(GND1) U29.A14(RTXI) U29.A17(GND2) U29.A20(GND3) U29.B20(GND4) U29.G19(SS_PG_N) U29.H9(GND5) U29.H10(GND6) U29.H11(GND7) U29.H12(GND8) U29.H13(GND9) U29.J9(GND10) U29.J10(GND11) U29.J11(GND12) U29.J12(GND13) U29.J13(GND14) U29.K9(GND15) U29.K10(GND16) U29.K11(GND17) U29.K12(GND18) U29.K13(GND19) U29.L9(GND20) U29.L10(GND21) U29.L11(GND22) U29.L12(GND23) U29.L13(GND24) U29.M9(GND25) U29.M10(GND26) U29.M11(GND27) U29.M12(GND28) U29.M13(GND29) U29.N9(GND30) U29.N10(GND31) U29.N11(GND32) U29.N12(GND33) U29.N13(GND34) U29.Y1(GND35) U29.Y20(GND36) U30.2(GND) U31.A1(GND1) U31.A2(GND2) U31.A5(GND3) U31.A6(GND4) U31.A7(GND5) U31.A17(GND6) U31.A27(GND7) U31.A34(GND8) U31.AA1(GND9) U31.AA2(GND10) U31.AA5(GND11) U31.AA7(GND12) U31.AA8(GND13) U31.AA9(GND14) U31.AA11(GND15) U31.AA13(GND16) U31.AA15(GND17) U31.AA17(GND18) U31.AA19(GND19) U31.AA21(GND20) U31.AA27(GND21) U31.AB3(GND22) U31.AB4(GND23) U31.AB7(GND24) U31.AB10(GND25) U31.AB12(GND26) U31.AB14(GND27) U31.AB16(GND28) U31.AB18(GND29) U31.AB20(GND30) U31.AB22(GND31) U31.AB24(GND32) U31.AB34(GND33) U31.AC1(GND34) U31.AC3(MGTHRXN3_115) U31.AC4(MGTHRXP3_115) U31.AC5(GND35) U31.AC7(GND36) U31.AC8(M0_0) U31.AC11(GND37) U31.AC13(GND38) U31.AC21(GND39) U31.AC31(GND40) U31.AD4(GND41) U31.AD7(GND42) U31.AD8(GND43) U31.AD18(GND44) U31.AD28(GND45) U31.AE1(GND46) U31.AE2(GND47) U31.AE3(MGTHRXN2_115) U31.AE4(MGTHRXP2_115) U31.AE5(GND48) U31.AE7(GND49) U31.AE15(GND50) U31.AE25(GND51) U31.AF3(GND52) U31.AF4(GND53) U31.AF5(MGTHRXN1_115) U31.AF6(MGTHRXP1_115) U31.AF7(GND54) U31.AF12(GND55) U31.AF22(GND56) U31.AF32(GND57) U31.AG1(GND58) U31.AG3(MGTHRXN0_115) U31.AG4(MGTHRXP0_115) U31.AG5(GND59) U31.AG7(GND60) U31.AG9(GND61) U31.AG19(GND62) U31.AG29(GND63) U31.AH4(GND64) U31.AH7(GND65) U31.AH16(GND66) U31.AH26(GND67) U31.AJ1(GND68) U31.AJ2(GND69) U31.AJ3(MGTHRXN3_114) U31.AJ4(MGTHRXP3_114) U31.AJ5(GND70) U31.AJ7(GND71) U31.AJ13(GND72) U31.AJ23(GND73) U31.AJ33(GND74) U31.AK3(GND75) U31.AK4(GND76) U31.AK7(GND77) U31.AK10(GND78) U31.AK20(GND79) U31.AK30(GND80) U31.AL1(GND81) U31.AL3(MGTHRXN2_114) U31.AL4(MGTHRXP2_114) U31.AL5(GND82) U31.AL7(GND83) U31.AL17(GND84) U31.AL27(GND85) U31.AM4(GND86) U31.AM5(MGTHRXN1_114) U31.AM6(MGTHRXP1_114) U31.AM7(GND87) U31.AM8(GND88) U31.AM14(GND89) U31.AM24(GND90) U31.AM34(GND91) U31.AN1(GND92) U31.AN2(GND93) U31.AN5(GND94) U31.AN8(GND95) U31.AN11(GND96) U31.AN21(GND97) U31.AN31(GND98) U31.AP3(GND99) U31.AP4(GND100) U31.AP5(MGTHRXN0_114) U31.AP6(MGTHRXP0_114) U31.AP8(GND101) U31.AP18(GND102) U31.AP28(GND103) U31.B3(GND104) U31.B4(GND105) U31.B7(GND106) U31.B14(GND107) U31.B24(GND108) U31.C1(GND109) U31.C5(GND110) U31.C7(GND111) U31.C11(GND112) U31.C21(GND113) U31.C31(GND114) U31.D4(GND115) U31.D7(GND116) U31.D8(GND117) U31.D18(GND118) U31.D28(GND119) U31.E1(GND120) U31.E2(GND121) U31.E5(GND122) U31.E7(GND123) U31.E15(GND124) U31.E25(GND125) U31.F3(GND126) U31.F4(GND127) U31.F7(GND128) U31.F12(GND129) U31.F22(GND130) U31.F32(GND131) U31.G1(GND132) U31.G5(GND133) U31.G7(GND134) U31.G9(GND135) U31.G19(GND136) U31.G29(GND137) U31.H4(GND138) U31.H7(GND139) U31.H16(GND140) U31.H26(GND141) U31.J1(GND142) U31.J2(GND143) U31.J5(GND144) U31.J7(GND145) U31.J13(GND146) U31.J23(GND147) U31.J33(GND148) U31.K3(GND149) U31.K4(GND150) U31.K7(GND151) U31.K10(GND152) U31.K20(GND153) U31.K30(GND154) U31.L1(GND155) U31.L5(GND156) U31.L7(GND157) U31.L17(GND158) U31.L27(GND159) U31.M4(GND160) U31.M7(GND161) U31.M14(GND162) U31.M22(GND163) U31.M24(GND164) U31.M34(GND165) U31.N1(GND166) U31.N2(GND167) U31.N5(GND168) U31.N7(GND169) U31.N11(GND170) U31.N13(GND171) U31.N15(GND172) U31.N17(GND173) U31.N19(GND174) U31.N21(GND175) U31.N31(GND176) U31.P3(GND177) U31.P4(GND178) U31.P7(GND179) U31.P8(GND180) U31.P9(VCCBATT_0) U31.P10(GND181) U31.P12(GND182) U31.P14(GND183) U31.P16(GND184) U31.P18(GND185) U31.P20(GND186) U31.P22(GND187) U31.P28(GND188) U31.R1(GND189) U31.R3(MGTHRXN3_116) U31.R4(MGTHRXP3_116) U31.R5(GND190) U31.R9(GND191) U31.R11(GND192) U31.R13(GND193) U31.R15(GND194) U31.R17(GND195) U31.R19(GND196) U31.R21(GND197) U31.R25(GND198) U31.T4(GND199) U31.T7(GND200) U31.T10(GND201) U31.T12(GND202) U31.T14(GND203) U31.T18(GND204) U31.T20(GND205) U31.T22(GND206) U31.T32(GND207) U31.U1(GND208) U31.U2(GND209) U31.U3(MGTHRXN2_116) U31.U4(MGTHRXP2_116) U31.U5(GND210) U31.U7(GND211) U31.U9(GND212) U31.U11(GND213) U31.U13(GND214) U31.U15(GND215) U31.U16(VN_0) U31.U17(VP_0) U31.U19(GND216) U31.U21(GND217) U31.U29(GND218) U31.V3(GND219) U31.V4(GND220) U31.V7(GND221) U31.V9(CFGBVS_0) U31.V10(GND222) U31.V12(GND223) U31.V14(GND224) U31.V18(GND225) U31.V20(GND226) U31.V22(GND227) U31.V26(GND228) U31.W1(GND229) U31.W5(GND230) U31.W7(GND231) U31.W9(GND232) U31.W11(GND233) U31.W13(GND234) U31.W15(GND235) U31.W16(DXN_0) U31.W17(DXP_0) U31.W19(GND236) U31.W21(GND237) U31.W23(GND238) U31.W33(GND239) U31.Y4(GND240) U31.Y5(GND241) U31.Y6(GND242) U31.Y7(GND243) U31.Y10(GND244) U31.Y12(GND245) U31.Y14(GND246) U31.Y16(GND247) U31.Y18(GND248) U31.Y20(GND249) U31.Y22(GND250) U31.Y30(GND251) U32.5(GND) U33.5(GND) U34.3(GND) U35.4(PGND) U35.8(GND) U35.PAD U36.10(VSS) U37.11(GND1) U37.12(GND2) U37.13(GND3) U37.22(OE_N) U37.PAD U38.2(E1) U38.4(VSS) U38.7(WC_N) U39.4(PGND) U39.8(GND) U39.PAD U40.3(GND) U41.4(GND) U42.5(GND) U43.2(A) U43.3(GND) U44.2(GND) V1.2(N2) Y1.2(GND) Y1.4(GND1)
VCC1V5: C16.1(N1) C17.1(N1) C40.1(N1) C41.1(N1) C136.2(N2) C137.2(N2) C181.2(N2) C182.2(N2) C186.P(N1) C205.2(N2) C221.1(N1) C223.1(N1) C224.1(N1) C225.1(N1) C241.2(N2) C242.2(N2) C250.2(N2) C264.2(N2) C265.2(N2) C270.2(N2) C272.2(N2) C274.2(N2) C283.1(N1) C284.2(N2) C286.2(N2) C288.2(N2) C291.P(N1) C302.1(N1) C309.2(N2) C318.2(N2) C319.1(N1) C331.1(N1) CN3.5(N5) CN3.6(N6) CN3.7(N7) CN3.8(N8) CN4.5(N5) CN4.6(N6) CN4.7(N7) CN4.8(N8) CN5.1(N1) CN5.2(N2) CN5.3(N3) CN5.4(N4) CN6.1(N1) CN6.2(N2) CN6.3(N3) CN6.4(N4) CN11.5(N5) CN11.6(N6) CN11.7(N7) CN11.8(N8) CN12.5(N5) CN12.6(N6) CN12.7(N7) CN12.8(N8) CN13.5(N5) CN13.6(N6) CN13.7(N7) CN13.8(N8) CN14.5(N5) CN14.6(N6) CN14.7(N7) CN14.8(N8) CN15.1(N1) CN15.2(N2) CN15.3(N3) CN15.4(N4) CN16.1(N1) CN16.2(N2) CN16.3(N3) CN16.4(N4) CN17.1(N1) CN17.2(N2) CN17.3(N3) CN17.4(N4) CN18.1(N1) CN18.2(N2) CN18.3(N3) CN18.4(N4) P5.75(N39) P5.76(N39) P5.81(N42) P5.82(N42) P5.87(N45) P5.88(N45) P5.93(N48) P5.94(N48) P5.99(N51) P5.100(N51) P5.105(N54) P5.106(N54) P5.111(N57) P5.112(N57) P5.117(N60) P5.118(N60) P5.123(N63) P5.124(N63) P6.75(N39) P6.76(N39) P6.81(N42) P6.82(N42) P6.87(N45) P6.88(N45) P6.93(N48) P6.94(N48) P6.99(N51) P6.100(N51) P6.105(N54) P6.106(N54) P6.111(N57) P6.112(N57) P6.117(N60) P6.118(N60) P6.123(N63) P6.124(N63) R13.2(N2) R22.1(N1) R104.2(N2) R106.2(N2) R108.2(N2) R109.2(N2) R114.2(N2) R115.2(N2) R116.2(N2) R117.2(N2) R177.1(N1) R232.1(N1) R240.1(N1) R249.2(N2) R251.2(N2) R253.2(N2) R255.2(N2) R292.2(N2) R298.2(N2) R316.1(N1) U7.12(SENSEP) U7.13(VIN) U31.AA32(VCCO_16_1) U31.AB29(VCCO_16_2) U31.AC16(VCCO_35_1) U31.AD13(VCCO_34_1) U31.AE10(VCCO_34_2) U31.AE20(VCCO_36_1) U31.AF17(VCCO_35_2) U31.AG14(VCCO_35_3) U31.AH11(VCCO_34_3) U31.AH21(VCCO_36_2) U31.AJ8(VCCO_34_4) U31.AJ18(VCCO_35_4) U31.AK15(VCCO_35_5) U31.AK25(VCCO_36_3) U31.AL12(VCCO_34_5) U31.AL22(VCCO_36_4) U31.AM9(VCCO_34_6) U31.AM19(VCCO_36_5) U31.AN16(VCCO_35_6) U31.AP13(VCCO_34_7) U31.AP23(VCCO_36_6) U31.G34(VCCO_18_1) U31.H31(VCCO_18_2) U31.J28(VCCO_18_3) U31.K25(VCCO_18_4) U31.L22(VCCO_18_5) U31.L32(VCCO_18_6) U31.M29(VCCO_18_7) U31.N26(VCCO_17_1) U31.P23(VCCO_17_2) U31.P33(VCCO_17_3) U31.R30(VCCO_17_4) U31.T27(VCCO_17_5) U31.U24(VCCO_16_3) U31.U34(VCCO_17_6) U31.V31(VCCO_16_4) U31.W28(VCCO_16_5) U31.Y25(VCCO_16_6) U35.2(VLDOIN) U39.2(VLDOIN)
VCC3V3: C58.P(N1) C60.2(N2) C61.2(N2) C65.2(N2) C66.2(N2) C80.2(N2) C81.2(N2) C82.2(N2) C83.2(N2) C95.1(N1) C126.1(N1) C128.1(N1) C131.2(N2) C143.2(N2) C152.1(N1) C154.1(N1) C156.1(N1) C158.1(N1) C160.1(N1) C162.1(N1) C163.2(N2) C168.2(N2) C169.2(N2) C170.2(N2) C171.2(N2) C172.2(N2) C173.2(N2) C177.2(N2) C178.2(N2) C179.2(N2) C180.2(N2) C187.2(N2) C188.2(N2) C192.2(N2) C194.2(N2) C195.2(N2) C196.2(N2) C197.2(N2) C198.2(N2) C200.2(N2) C201.2(N2) C203.2(N2) C204.2(N2) C207.1(N1) C209.1(N1) C211.1(N1) C212.2(N2) C213.2(N2) C214.2(N2) C215.2(N2) C216.2(N2) C217.2(N2) C218.2(N2) C219.2(N2) C229.2(N2) C246.1(N1) C247.1(N1) C248.1(N1) C335.1(N1) C339.2(N2) C342.1(N1) F2.1(N1) P5.199(N68) P6.199(N68) Q12.2(S) R73.1(N1) R76.1(N1) R91.1(N1) R93.1(N1) R119.2(N2) R132.2(N2) R157.2(N2) R163.1(N1) R165.2(N2) R169.2(N2) R171.2(N2) R172.2(N2) R173.2(N2) R178.2(N2) R179.2(N2) R180.2(N2) R181.2(N2) R182.2(N2) R183.2(N2) R184.2(N2) R185.2(N2) R186.2(N2) R187.2(N2) R188.2(N2) R197.2(N2) R198.2(N2) R223.1(N1) R227.1(N1) R228.1(N1) R229.1(N1) R230.1(N1) R239.1(N1) R246.1(N1) R256.2(N2) R291.1(N1) R307.1(N1) R317.1(N1) R318.1(N1) R558.2(N2) R660.2(N2) U3.1(VCC) U4.1(VCC) U5.1(VCC) U6.1(VCC) U7.1(VCC) U8.1(VCC) U11.8(VCC1) U11.13(VCC) U12.1(VSCA) U12.2(VSI2C) U12.4(VSREFOUT) U12.5(VSX) U12.10(VSCB) U12.14(VSVB) U12.24(VSFB) U12.27(VSFA) U12.38(VSVA) U13.8(VCC1) U13.13(VCC) U14.1(VCC) U15.1(VCC) U15.12(SENSEP) U15.13(VIN) U16.1(VCC) U18.8(VIN) U19.1(VIN) U20.1(IN) U20.3(EN) U21.2(IN) U22.6(VCCB) U24.5(VCC) U28.16(VCCB) U29.A16(VDDRTC) U29.D19(VDDUSB1) U29.G20(VDDUSB2) U33.8(VDD) U35.10(VIN) U36.20(VDD) U37.23(VCCB1) U37.24(VCCB2) U38.1(E0) U38.3(E2) U38.8(VCC) U39.10(VIN) U42.8(VDD)
VIN: D1.C(N) D2.C(N) F1.2(N2) Q11.2(S) R29.2(N2) R50.1(N1) R58.2(N2) R59.2(N2) R218.1(N1) R244.2(N2) R245.2(N2)
VIN_12V: C1.1(N1) C6.1(N1) C13.1(N1) C19.1(N1) C22.1(N1) C25.1(N1) C35.1(N1) C44.1(N1) C109.1(N1) C112.1(N1) C118.1(N1) C119.1(N1) C313.P(N1) D3.C(N) P4.2(N2) Q3.1(N1) Q3.2(N2) Q3.3(N3) R17.2(N2) R199.2(N2) R206.2(N2) R212.2(N2) R234.1(N1) R273.1(N1) TP4.1(N1) U1.6(PVIN3) U1.7(PVIN4) U1.22(PVIN2_1) U1.23(PVIN2_2) U1.24(PVIN2_3) U1.36(PVIN1_1) U1.37(PVIN1_2) U1.38(PVIN1_3) U2.6(PVIN3) U2.7(PVIN4) U2.22(PVIN2_1) U2.23(PVIN2_2) U2.24(PVIN2_3) U2.36(PVIN1_1) U2.37(PVIN1_2) U2.38(PVIN1_3) U10.1(VCC) U27.6(PVIN3) U27.7(PVIN4) U27.22(PVIN2_1) U27.23(PVIN2_2) U27.24(PVIN2_3) U27.36(PVIN1_1) U27.37(PVIN1_2) U27.38(PVIN1_3)
AD9577_OUT0_N: C59.2(N2) U11.4(CLK_N)
AD9577_OUT0_P: C63.2(N2) U11.1(CLK)
AD9577_OUT1_N: R64.2(N2) R67.1(N1) U12.28(OUT1N)
AD9577_OUT1_P: R68.1(N1) R69.2(N2) U12.29(OUT1P)
AD9577_OUT2_N: C191.2(N2) U13.4(CLK_N)
AD9577_OUT2_P: C190.2(N2) U13.1(CLK)
